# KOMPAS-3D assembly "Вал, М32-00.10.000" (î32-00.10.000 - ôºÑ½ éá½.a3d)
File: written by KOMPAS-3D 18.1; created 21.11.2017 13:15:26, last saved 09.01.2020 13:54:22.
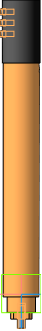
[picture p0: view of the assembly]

Document properties: Автор: Милов; Организация: Милов; Полное имя файла: D:\Magna\Магна Ins\Магна ins 32\Для Караби Магна 32\М32-00.10.000 - Узел Вал.a3d

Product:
- Part/product: Вал  | designation М32-00.10.000  | pos. 0
    Масса: 1.67698
    Раздел спецификации: Сборочные единицы
    Форматы листов документа: A3
    source file: C:\Users\User\Desktop\Вал _ М32-00.10.000.spw, М32-00.10.000 - Вал.cdw
  - Component [detail]: Вал  | designation М32-00.10.001  | pos. 1  | Масса: 1.30054; Раздел спецификации: Детали; Форматы листов документа: A3; Примечание: см. заказ; source file: М32-00.10.001 - Вал.cdw, М32-00.10.001 - Вал.m3d
  - Component [standard]: Винт A.М10-6gx30.21.12Х18Н10Т ГОСТ 11074-93  | pos. 7
      Материал: Сталь 12Х18Н10Т ГОСТ 5632-72 (density 1000 kg/m3)
      Масса: 0.01408
      Раздел спецификации: Стандартные изделия
      Примечание: Нерж.
      additional columns: А.М10-6gx30.21.12Х18Н10Т; Сталь 12Х18Н10Т ГОСТ 5632-72
      source file: C:\Program Files\ASCON\KOMPAS-3D v18\Libs\PartLib\DATA\VAULT\methods\kompas\3d\PLib_Screw_GOST_11074-84_900.m3d
  - Component [standard]: Винт A.М8-6gx20.21.12Х18Н10Т ГОСТ 8878-93  | qty 3  | pos. 6
      Материал: Сталь 12Х18Н10Т ГОСТ 5632-72 (density 1000 kg/m3)
      Масса: 0.0054
      Раздел спецификации: Стандартные изделия
      Примечание: Нерж.
      additional columns: А.М8-6gx20.21.12Х18Н10Т; Сталь 12Х18Н10Т ГОСТ 5632-72
      source file: C:\Program Files\ASCON\KOMPAS-3D v18\Libs\PartLib\DATA\VAULT\methods\kompas\3d\PLib_Screw_GOST_8878-84_900.m3d
  - Component [detail]: Фиксатор  | designation М40-00.10.002-02  | pos. 3
      Материал: Сталь 12Х18Н10Т ГОСТ 5632-72 (density 7900 kg/m3)
      Масса: 0.346158
      Раздел спецификации: Детали
      Форматы листов документа: A3
      Примечание: заим.
      source file: C:\Users\Kon\Desktop\Переработка Лифлянд\Магна ins 40\М40-00.10.002 - Фиксатор.cdw, М40-00.10.002 - Фиксатор.m3d

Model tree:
1. Массив по образцу:4  (3 pattern instances)
2. Сечение поверхностью:1  (with: Операция выдавливания:2, Вырезать элемент выдавливания:8, Операция выдавливания:1, Вырезать элемент выдавливания:4, Отверстие:1)
     Расстояние = -17.5

Referenced files in D:\Magna\Магна Ins\Магна ins 32\Для Караби Магна 32\: М32-00.10.001 - Вал.m3d, М32-00.10.001 - Вал.cdw, М40-00.10.002 - Фиксатор.m3d
Referenced files in C:\Program Files\ASCON\KOMPAS-3D v18\Libs\PartLib\DATA\VAULT\methods\kompas\3d\: PLib_Screw_GOST_11074-84_900.m3d, PLib_Screw_GOST_8878-84_900.m3d
Referenced files in C:\Users\Kon\Desktop\Переработка Лифлянд\Магна ins 40\: М40-00.10.002 - Фиксатор.cdw
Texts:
  Крепежное изделие ГОСТ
